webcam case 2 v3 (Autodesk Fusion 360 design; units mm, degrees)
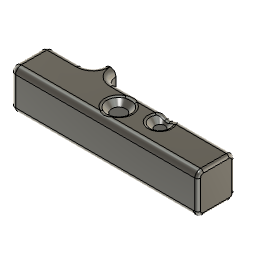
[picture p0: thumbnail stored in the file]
sketch "草图1" plane through (0, 0, 0) normal (0, 0, 1) x axis (1, 0, 0)
  line L1 (-31, -4.5) -> (31, -4.5)
  line L2 (-31, 4.5) -> (-31, -4.5)
  line L3 (31, 4.5) -> (-31, 4.5)
  line L4 (31, -4.5) -> (31, 4.5)
  line L5 (-31, 4.5) -> (31, -4.5)
  line L6 (31, 4.5) -> (-31, -4.5)
  line L7 (31, 0) -> (-31, 0)
  line L8 (-33, -6.5) -> (33, -6.5)
  line L9 (-33, 6.5) -> (-33, -6.5)
  line L10 (33, 6.5) -> (-33, 6.5)
  line L11 (33, -6.5) -> (33, 6.5)
  line L12 (-31.5, -5) -> (31.5, -5)
  line L13 (-31.5, 5) -> (-31.5, -5)
  line L14 (31.5, 5) -> (-31.5, 5)
  line L15 (31.5, -5) -> (31.5, 5)
  line L16 (29.5, -2.5) -> (-20.5, -2.5)
  circle C1 centre (29.5, 2.5) radius 0.975
  circle C2 centre (29.5, -2.5) radius 0.975
  circle C3 centre (-20.5, -2.5) radius 0.975
  circle C4 centre (-20.5, -2.5) radius 1.675
  circle C5 centre (29.5, 2.5) radius 1.675
  circle C6 centre (29.5, -2.5) radius 1.675
  circle C7 centre (-1.25, 0) radius 2.5
  circle C8 centre (10.75, 2.5) radius 1.75
  point P6 (0, 0)
  point P1 (0, 0)
  point P7 (-31, 0)
  point P8 (31, 0)
  point P23 (-1.25, 0)
  point P11 (-20.5, -2.5)
  point P25 (-20.5, -2.5)
  point P10 (29.5, -2.5)
  point P26 (29.5, -2.5)
  point P4 (-31, 4.5)
  point P5 (31, 4.5)
  point P2 (31, -4.5)
  point P9 (29.5, 2.5)
  point P24 (10.75, 2.5)
  horizontal L1
  perpendicular L1 L2
  parallel L1 L3
  parallel L2 L4
  coincident L5 P6
  coincident L6 P6
  coincident P1 P6
  midpoint L2 P7
  midpoint L4 P8
  symmetric L7 C1 C2
  equal C1 C3
  coincident L7 P23
  coincident P11 P25
  coincident P10 P26
  parallel L12 L16
  dimension "d1" distance P4 P5 = 62
  dimension "d2" distance P2 P5 = 9
  dimension "d3" diameter C1 = 1.95
  dimension "d4" distance L4 P9 = 1.5
  dimension "d5" distance L3 P9 = 2
  dimension "d7" = -2
  dimension "d8" = -0.5
  dimension "d9" = 0.7
  dimension "d10" = 0.7
  dimension "d11" = 0.7
  dimension "d12" distance P6 P23 = 1.25
  dimension "d13" diameter C7 = 5
  dimension "d14" diameter C8 = 3.5
  dimension "d17" distance P23 P24 = 12
  dimension "d47" distance L14 P24 = 2.5
  dimension "d52" distance P25 P26 = 50
extrude "拉伸1" new body sketch "草图1" profile of C1 C2 C3 L10 L9 L8 L11 L14 L12 L13 L15 C4 C5 C6 C7 C8 along normal blind 2
chamfer "倒角1" distance 2
chamfer "倒角2" distance 2
extrude "拉伸2" add sketch "草图1" profile of C1 C2 C3 C4 C5 C6 against normal blind 5.5
extrude "拉伸3" add sketch "草图1" profile of L10 L9 L8 L11 L14 L12 L13 L15 against normal blind 12
sketch "草图2" plane through (-31.5, 0, 0) normal (1, 0, 0) x axis (0, 1, 0)
  line L1 (-5, 0) -> (5, 0)
  line L2 (-5, -12) -> (-5, 0)
  line L3 (5, -12) -> (-5, -12)
  line L4 (5, 0) -> (5, -12)
  line L5 (-5, -12) -> (5, -12)
  line L6 (-5, -2) -> (-5, -12)
  line L7 (5, -2) -> (-5, -2)
  line L8 (5, -12) -> (5, -2)
  line L9 (5, -6) -> (-5, -6)
  point P8 (-5, -2)
  point P5 (5, -12)
  point P6 (5, -12)
  point P10 (-5, -6)
  point P11 (5, -6)
  horizontal L5
  vertical L6
  horizontal L7
  vertical L8
  coincident L2 P8
  coincident P5 P6
  coincident P10
  horizontal L9
  coincident L4 P11
  dimension "d26" distance L1 L7 = 2
  dimension "d28" distance L7 L9 = 4
extrude "拉伸4" cut sketch "草图2" profile of L2 L4 L6 L7 L8 L9 against normal blind 1.5
sketch "草图5" plane through (0, 6.5, 0) normal (0, 1, 0) x axis (-1, 0, 0)
  line L1 (33, 2) -> (33, -12)
  line L2 (-33, 2) -> (33, 2)
  line L3 (-33, -12) -> (-33, 2)
  line L4 (33, -12) -> (-33, -12)
  line L5 (1.25, -12) -> (1.25, 2)
  line L6 (12.75, -12) -> (12.75, 2)
  line L7 (16.75, -12) -> (16.75, 2)
  line L8 (12.75, -5) -> (16.75, -5)
  line L9 (14.75, 0) -> (14.75, -5)
  circle C1 centre (14.75, 0) radius 0.975
  circle C2 centre (14.75, -10) radius 0.975
  point P6 (1.25, 2)
  point P7 (1.25, -12)
  point P8 (12.75, 2)
  point P9 (12.75, -12)
  point P10 (16.75, 2)
  point P11 (16.75, -12)
  point P12 (16.75, -5)
  point P13 (12.75, -5)
  point P14 (14.75, -5)
  point P15 (14.75, 0)
  point P16 (14.75, 0)
  point P17 (14.75, -10)
  coincident L2 P6
  coincident L4 P7
  perpendicular L4 L5
  coincident L2 P8
  coincident L4 P9
  perpendicular L4 L6
  coincident L2 P10
  coincident L4 P11
  perpendicular L4 L7
  midpoint L7 P12
  midpoint L6 P13
  midpoint L8 P14
  perpendicular L8 L9
  coincident P15 P16
  symmetric L8 C1 C2
  dimension "d65" distance L1 L5 = 31.75 (= "29.25 mm + 2.5 mm")
  dimension "d66" distance L5 L6 = 11.5 (= "( 23 / 2 ) * 1 mm")
  dimension "d67" distance L6 L7 = 4
  dimension "d68" diameter C1 = 1.95
  dimension "d69" distance P16 P17 = 10
extrude "拉伸9" add sketch "草图5" profile of L2 L4 L6 L7 C1 C2 along normal blind 4
fillet "圆角10" radius 4
sketch "草图3" plane through (33, 0, 0) normal (1, 0, 0) x axis (0, 1, 0)
  line L1 (6.5, 2) -> (6.5, -12)
  line L2 (-6.5, 2) -> (6.5, 2)
  line L3 (-6.5, -12) -> (-6.5, 2)
  line L4 (6.5, -12) -> (-6.5, -12)
  line L5 (6.5, -5) -> (-6.5, -5)
  line L6 (6.5, -7) -> (-6.5, -7)
  line L7 (6.5, -12) -> (-6.5, -12)
  point P6 (-6.5, -5)
  point P7 (6.5, -5)
  point P8 (-6.5, -7)
  point P9 (6.5, -7)
  point P10 (-6.5, -12)
  point P11 (6.5, -12)
  midpoint L3 P6
  midpoint L1 P7
  coincident L3 P8
  coincident L1 P9
  perpendicular L1 L6
  coincident L3 P10
  coincident L1 P11
  perpendicular L1 L7
  dimension "d39" distance L5 L6 = 2
  dimension "d40" distance L6 L7 = 5
fillet "圆角1" radius 2
fillet "圆角2" radius 2
fillet "圆角4" radius 1.9
fillet "圆角9" radius 1
extrude "拉伸7" cut of existing geometry blind -1
fillet "圆角6" radius 1
fillet "圆角8" radius 1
